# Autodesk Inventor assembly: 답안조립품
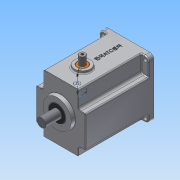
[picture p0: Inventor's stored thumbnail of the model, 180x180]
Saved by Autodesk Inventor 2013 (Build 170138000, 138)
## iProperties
Created: 2016-02
Part Number: 답안조립품
Document SubType Name: Assembly
Designer: Administrator
Mass: 2389.35 g
Surface Area: 1794.84 cm^2
Volume: 669.831 cm^3
Density: 3.5671 g/cm^3
Author: Administrator
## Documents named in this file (13)
- C:\Users\Administrator\Desktop\360212V1023\답안조립품.iam
- C:\Users\Administrator\Desktop\360212V1023\본체.ipt
- C:\Users\Administrator\Desktop\360212V1023\커버.ipt
- C:\Users\Administrator\Desktop\360212V1023\오일실 17 32 8.ipt
- C:\Users\Administrator\Desktop\360212V1023\오일실 8 22 7.ipt
- C:\Users\Administrator\Desktop\360212V1023\부시.ipt
- C:\Users\Administrator\Desktop\360212V1023\베어링 608.ipt
- C:\Users\Administrator\Desktop\360212V1023\베어링 6003.ipt
- C:\Users\Administrator\Desktop\360212V1023\볼트 M4 x 10.ipt
- C:\Users\Administrator\Desktop\360212V1023\슬라이더.ipt
- C:\Users\Administrator\Desktop\360212V1023\메인축.ipt
- C:\Users\Administrator\Desktop\360212V1023\서브축.ipt
- C:\Users\Administrator\Desktop\360212V1023\가변스프링1.ipt
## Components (3 placed, 2 different names)
1. ISO 4762 M4 x 10:1
2. ISO 4762 M4 x 10:2
3. 가변스프링1:1
